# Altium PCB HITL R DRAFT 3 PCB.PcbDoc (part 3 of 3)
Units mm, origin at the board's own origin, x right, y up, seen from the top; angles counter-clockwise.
Board outline 90 x 65 mm, 6 copper layers (L1, L2, L3, L4, L5, L6), stack 1.752 mm thick; 198 components, 194 nets, 830 pads, 458 vias.
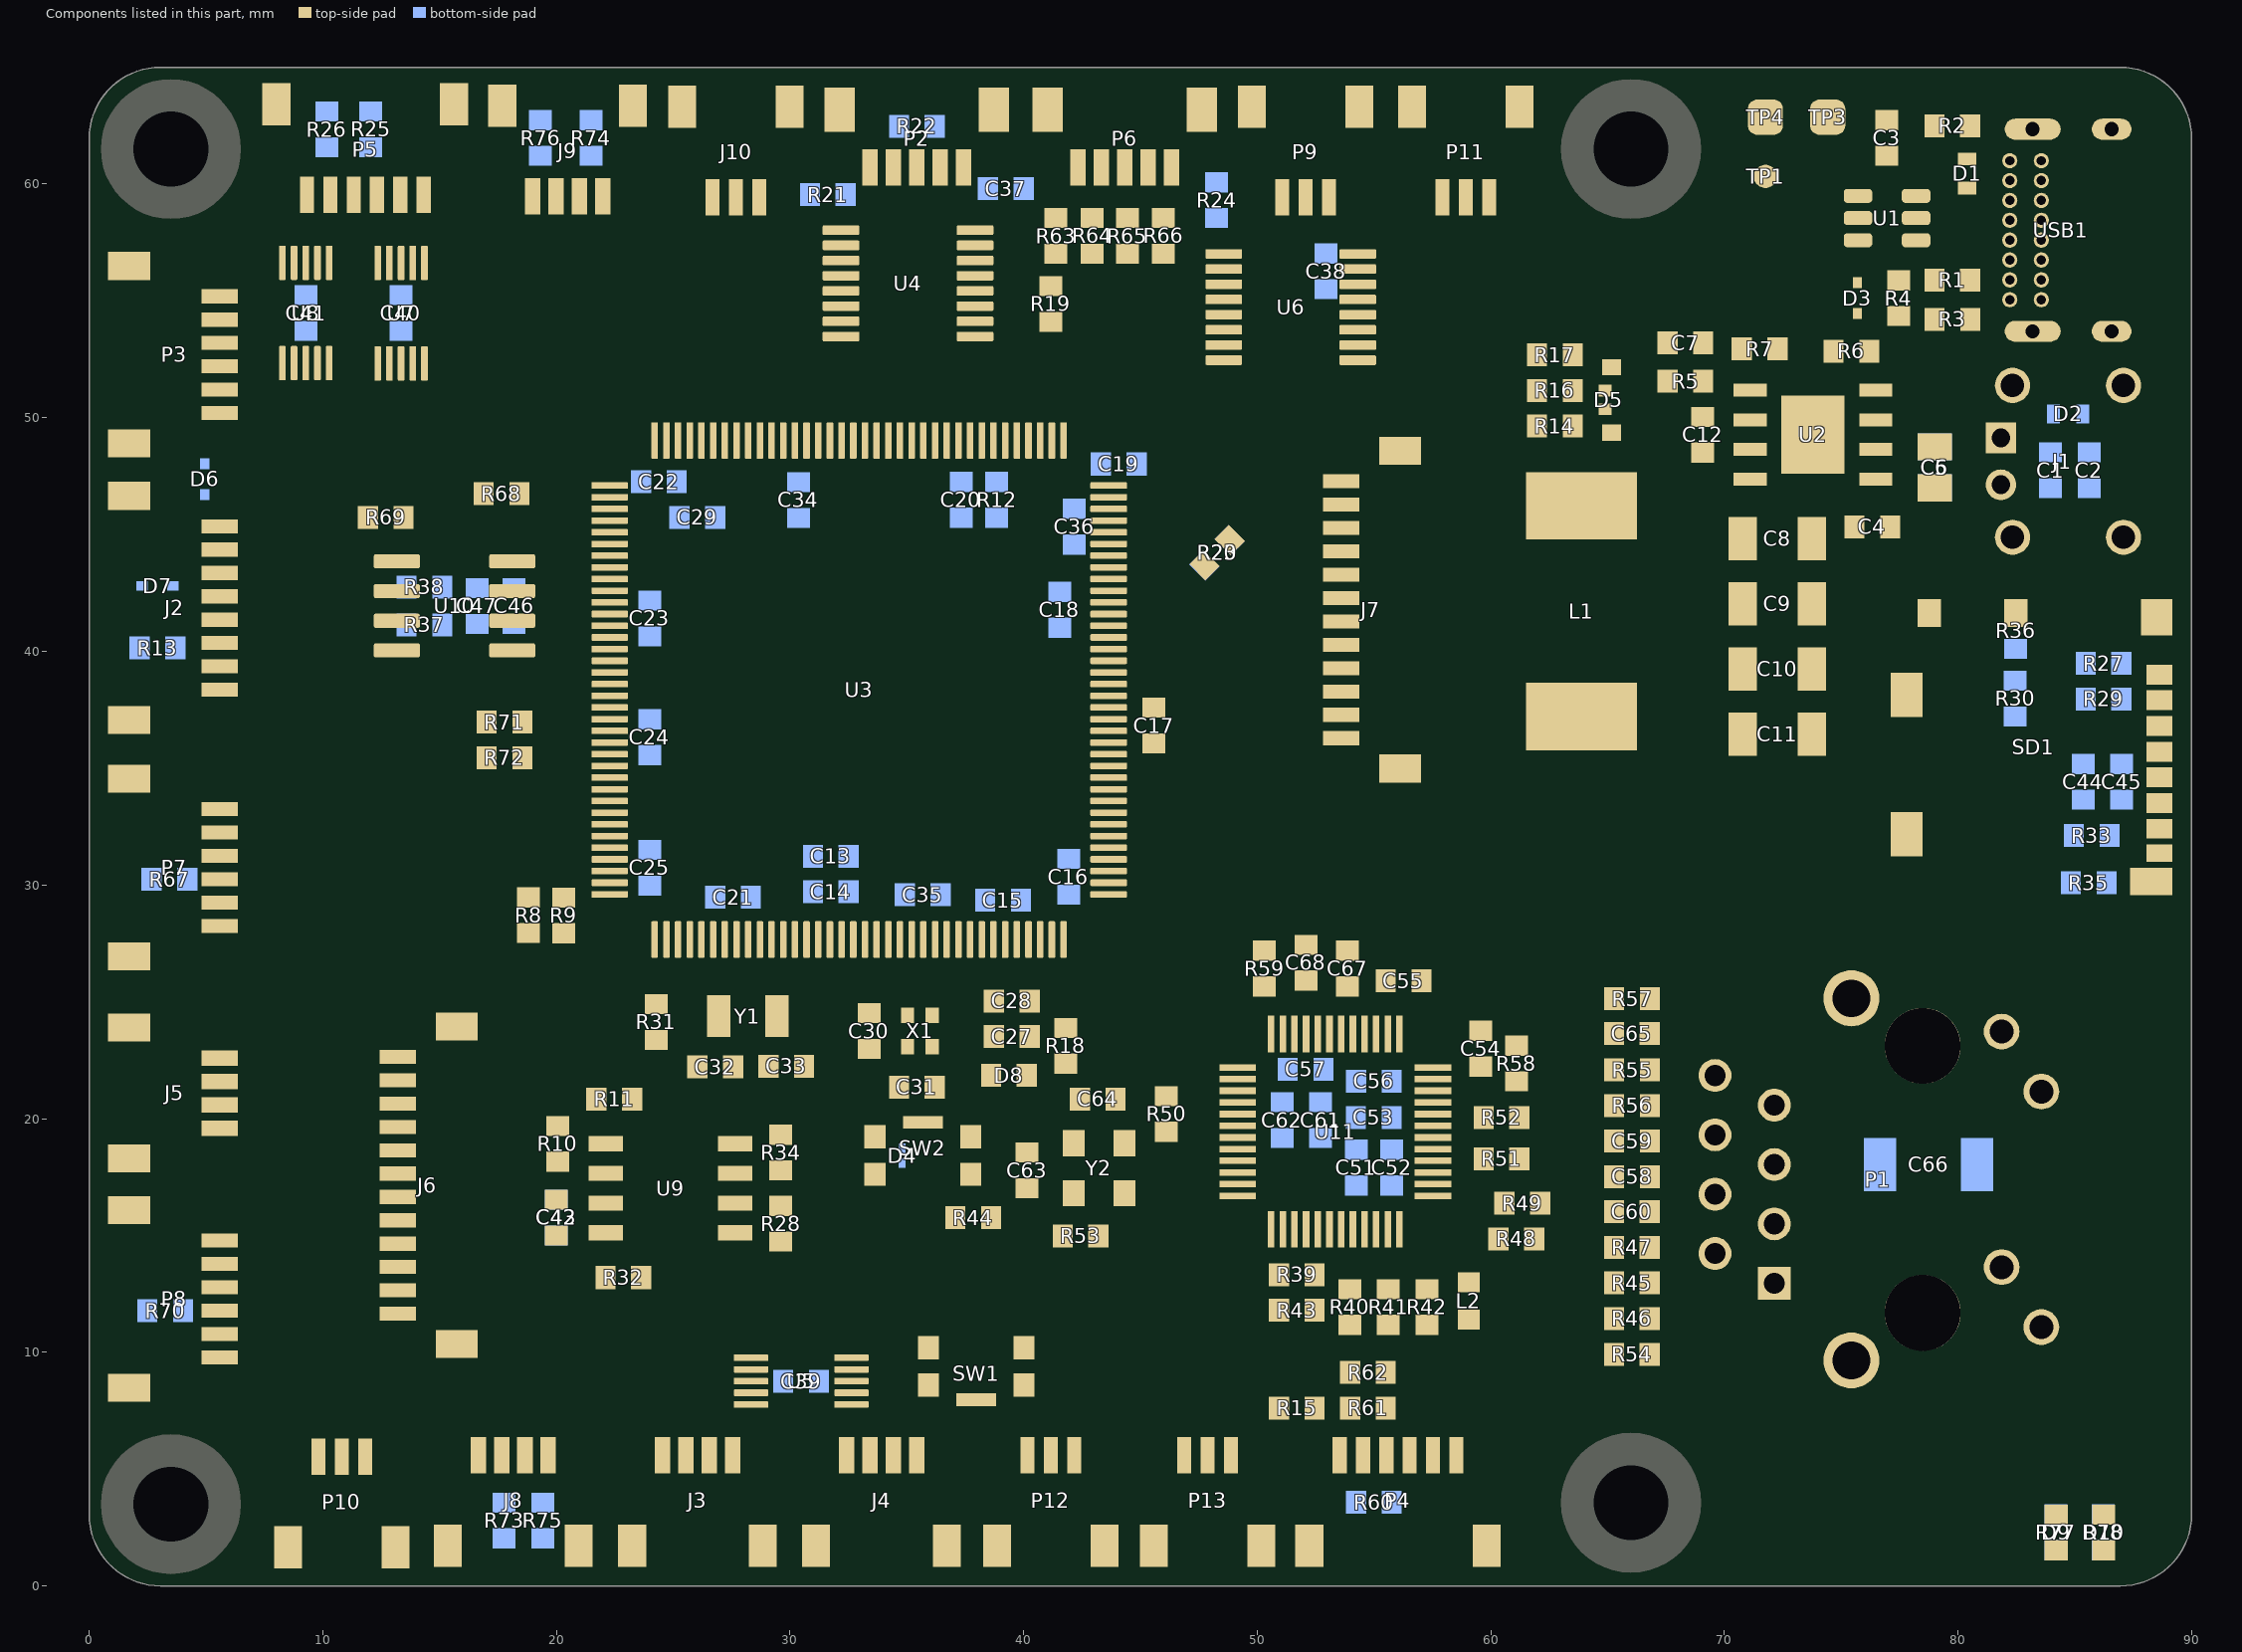
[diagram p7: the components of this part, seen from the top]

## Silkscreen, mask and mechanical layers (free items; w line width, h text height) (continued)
Mechanical 9:
  drawing of 249 lines, arcs and shapes, not listed
  text "1" at -84.782,155.186 h1.78
  text "3" at 41.838,155.186 h1.78
  text "4" at 105.507,155.186 h1.78
  text "5" at 168.981,155.186 h1.78
  text "6" at 232.583,155.16 h1.78
  text "A" at -114.153,126.154 h1.78
  text "A" at 261.742,126.128 h1.78
  text "DESIGN INFORMATION" at 210.803,108.539 h1.02
  text "MIN. TRACK WIDTH:" at 194.431,103.967 h1.02
  text "MIL" at 226.206,103.967 h1.02
  text "MIN. CLEARANCE:" at 194.431,100.614 h1.02
  text "MIL" at 226.206,100.614 h1.02
  text "MIN. VIA PAD SIZE:" at 194.431,97.261 h1.02
  text "MIL" at 226.206,97.261 h1.02
  text "0.05mm (2MIL)" at 212.084,93.662 h1.02
  text "MINIMUM ANNULAR RING" at 186.069,93.553 h1.02
  text "EXTERNAL" at 230.067,93.553 h1.02
  text "PER" at 191.149,90.555 h1.02
  text "IPC-D-275 CLASS 2 LEVEL C" at 196.737,90.555 h1.02
  text "+/-" at 224.569,87.685 h1.02
  text "MIL, HOLES" at 234.538,87.703 h1.02
  text "+/-" at 246.261,87.685 h1.02
  text "REGISTRATION TOLERANCES:" at 186.069,87.558 h1.02
  text "METAL" at 216.543,87.558 h1.02
  text "3" at 252.336,87.558 h1.02
  text "MIL" at 255.289,87.558 h1.02
  text "+/-" at 246.261,84.688 h1.02
  text "HOLE SIZE TOLERANCE (UNLESS OTHERWISE SPECIFIED):" at 186.069,84.561 h1.02
  text "3" at 252.336,84.561 h1.02
  text "MIL" at 255.289,84.561 h1.02
  text "MATERIAL:" at 184.169,79.241 h1.02
  text "FR-4 High Tg" at 209.225,75.676 h1.02
  text "FR-408" at 194.863,75.459 h1.02
  text "OTHER" at 232.658,75.459 h1.02
  text "X" at 205.291,75.366 h1.02
  text "62 MIL (1.6mm) +/-10%" at 202.993,71.326 h1.02
  text "THICKNESS:" at 186.069,71.217 h1.02
  text "X" at 199.738,71.217 h1.02
  text "OTHER" at 235.63,71.217 h1.02
  text "TOLERANCE:" at 186.069,67.204 h1.02
  text "X" at 207.387,67.204 h1.02
  text "ANSI IPC-6012 TYPE 3 CLASS 2" at 212.135,67.204 h1.02
  text "B" at -114.153,65.702 h1.78
  text "B" at 261.742,65.676 h1.78
  text "OTHER +/-" at 212.135,63.241 h1.02
  text "BOW & TWIST:" at 186.069,59.253 h1.02
  text "X" at 207.387,59.253 h1.02
  text "ANSI IPC-6012 TYPE 3 CLASS 2" at 212.135,59.253 h1.02
  text "OTHER +/-" at 212.135,55.227 h1.02
  text "DRILLING:" at 184.169,51.71 h1.02
  text "REFERENCE:" at 186.069,48.738 h1.02
  text "X" at 202.534,48.738 h1.02
  text "AS SHOWN" at 207.283,48.738 h1.02
  text "X" at 225.419,48.738 h1.02
  text "NC_DRILL FILES" at 228.899,48.738 h1.02
  text "PTH COPPER THICKNESS:" at 186.069,44.725 h1.02
  text "X" at 214.776,44.725 h1.02
  text "20-30 um" at 218.256,44.725 h1.02
  text "OTHER" at 236.468,44.725 h1.02
  text "BOARD FINISH:" at 184.169,40.686 h1.02
  text "SILKSCREEN:" at 188.112,37.689 h1.02
  text "X" at 212.211,37.689 h1.02
  text "TOP" at 215.411,37.689 h1.02
  text "X" at 225.165,37.689 h1.02
  text "BOTTOM" at 228.391,37.689 h1.02
  text "SILKSCREEN COLOR:" at 188.112,33.447 h1.02
  text "X" at 212.185,33.447 h1.02
  text "WHITE" at 215.411,33.447 h1.02
  text "OTHER" at 228.391,33.447 h1.02
  text "X" at 230.411,29.519 h1.02
  text "GREEN" at 218.739,29.403 h1.02
  text "OTHER" at 234.436,29.403 h1.02
  text "RED" at 243.416,29.316 h1.02
  text "SOLDER RESIST COLOR:" at 188.112,29.129 h1.02
  text "X" at 215.512,25.085 h1.02
  text "MATTE" at 218.739,25.085 h1.02
  text "SEMI-GLOSS" at 234.424,25.069 h1.02
  text "IMMERSION GOLD (ENIG)" at 211.119,20.297 h1.02
  text "ENEPIG" at 245.092,20.214 h1.02
  text "SURFACE FINISH:" at 184.169,20.188 h1.02
  text "X" at 206.37,20.188 h1.02
  text "IMM. TIN/SILVER OR EQUIV" at 192.54,16.2 h1.02
  text "OTHER" at 228.899,16.2 h1.02
  text "ARRAY/PANEL:" at 184.169,11.654 h1.02
  text "CUT AND TRIM PER M1 BOARD OUTLINE" at 211.119,11.545 h1.02
  text "N.C. ROUTE" at 211.119,7.691 h1.02
  text "X" at 228.365,7.691 h1.02
  text "V. SCORE" at 233.115,7.691 h1.02
  text "C" at -114.153,5.377 h1.78
  text "C" at 261.742,5.351 h1.78
  text "CERTIFICATION:" at 184.169,4.212 h1.02
  text "MATERIALS AND WORKMANSHIP FOR ALL PCBS" at 202.584,4.212 h1.02
  text "TO MEET OR EXCEED THE REQUIREMENTS OF:" at 202.584,1.722 h1.02
  text "X" at 193.098,-1.745 h1.02
  text "ANSI IPC-A-600F CLASS ->" at 196.628,-1.745 h1.02
  text "X" at 238.26,-1.745 h1.02
  text "2" at 241.281,-1.745 h1.02
  text "1" at 233.28,-1.783 h1.02
  text "3" at 250.273,-1.783 h1.02
  text "X" at 213.775,-5.796 h1.02
  text "RoHS" at 217.253,-5.796 h1.02
  text "OTHER" at 233.621,-5.796 h1.02
  text "PER ORDER" at 243.706,-5.796 h1.02
  text "ALL BOARDS MUST MEET OR EXCEED EE400D REQUIREMENTS." at 184.869,-10.003 h1.02
  text "ADDITIONAL REQUIREMENTS:" at 184.169,-17.455 h1.02
  text "MICROSECTION:" at 186.069,-20.376 h1.02
  text "YES" at 209.074,-20.376 h1.02
  text "REQUIRED" at 230.956,-24.342 h1.02
  text "BARE BOARD ELEC. TEST:" at 186.069,-24.414 h1.02
  text "NONE" at 219.234,-24.414 h1.02
  text "X" at 227.73,-24.414 h1.02
  text "PER ORDER" at 245.993,-24.414 h1.02
  text "DEESC" at 197.62,-35.962 h5.08
  text "PROJECT TITLE:" at 184.526,-41.918 h1.14
  text "DESIGNED FOR:" at 184.526,-49.564 h1.14
  text "D" at -114.178,-54.847 h1.78
  text "D" at 261.742,-54.847 h1.78
  text "COMPONENTS MARKED 'DNI' SHOULD NOT BE POPULATED." at -74.3,-57.057 h1.02
  text "FILE NAME:" at 184.526,-57.184 h1.14
  text "ASSEMBLY VARIANT:" at -74.313,-59.99 h1.02
  text ".VariantName" at -47.998,-59.99 h1.02
  text ".PCB_File_Name_No_Path" at 185.796,-60.232 h1.78
  text "NOTICE OF OWNERSHIP AND INTELLECTUAL PROPERTY:" at 66.734,-64.258 h1.27
  text "PROJECT MANAGER:" at 184.526,-64.55 h1.14
  text "LAYOUT BY:" at 222.753,-64.55 h1.14
  text "PCB VIEWED FROM TOP SIDE" at -109.403,-65.621 h1.02
  text "THIS SENIOR DESIGN PROJECT IS INDEPENDENTLY CONCEIVED, DESIGNED, AND FUNDED ENTIRELY" at 66.734,-66.29 h1.27
  text "BY THE PROJECT TEAM. NO FINANCIAL SUPPORT, PROPRIETARY MATERIALS, OR DIRECTED" at 66.734,-68.322 h1.27
  text "JON TOLDEN" at 185.796,-68.487 h1.78
  text "THOMAS STOLPE" at 224.036,-68.487 h1.78
  text "RESEARCH WERE PROVIDED BY CSULB OR ITS AFFILIATES. ALL INTELLECTUAL PROPERTY," at 66.734,-70.354 h1.27
  text "SOFTWARE BY: BAO PHAM" at -109.403,-70.701 h1.02
  text "DESIGNS, HARDWARE, SOFTWARE, AND DOCUMENTATION REMAIN THE SOLE PROPERTY OF THE" at 66.734,-72.386 h1.27
  text "ALTIUM DESIGNER VERSION:" at 222.753,-72.424 h1.14
  text "PROJECT TEAM. CSULB CLAIMS NO OWNERSHIP, LICENSING, OR COMMERCIAL RIGHTS BEYOND" at 66.734,-74.418 h1.27
  text "POWER SCHEME BY: AUTUMN AGUILAR" at -109.403,-75.781 h1.02
  text ".print_Scale" at 185.796,-75.81 h1.78
  text ".Application_BuildNumber" at 224.036,-75.81 h1.78
  text "GENERATED    :" at -46.449,-76.001 h1.02
  text ".Print_Date" at -24.364,-76.001 h1.02
  text ".Print_Date" at -24.364,-76.001 h1.02
  text ".Print_Time" at -5.847,-76.001 h1.02
  text ".Print_Time" at -5.847,-76.001 h1.02
  text "ACADEMIC EVALUATION PURPOSES." at 66.734,-76.45 h1.27
  text "1" at -84.807,-81.06 h1.78
  text "2" at -21.417,-81.06 h1.78
  text "4" at 105.481,-81.06 h1.78
  text "5" at 168.956,-81.06 h1.78
  text "6" at 232.583,-81.06 h1.78

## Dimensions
3.048,0 to 3.5,61.5 on Dimensions
0,61.952 to 66,61.5 on Dimensions
3.5,61.5 to 0,56.952 on Dimensions
3.5,61.5 to 3.5,3.5 on Dimensions
3.5,61.5 to 66,61.5 on Dimensions
3.048,65 to 3.048,0 on Dimensions
0,56.952 to 90,61.952 on Dimensions
-103.599,-59.127 to -78.199,-59.127 on Mechanical 9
